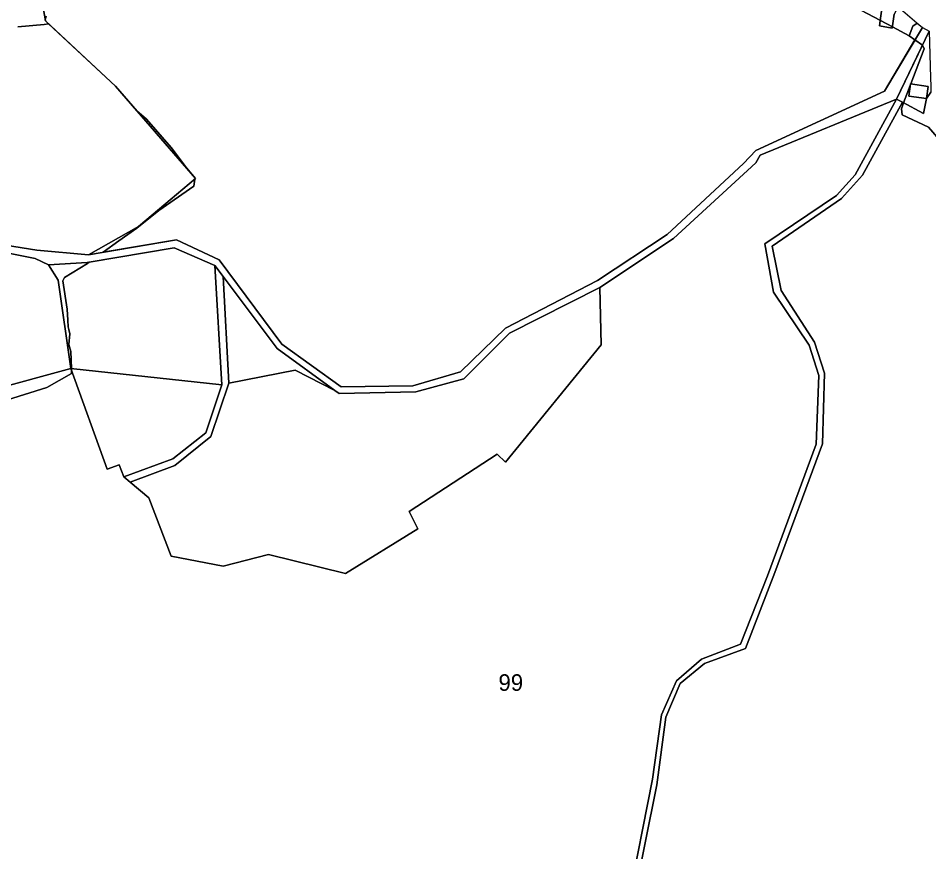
# Model space of a CAD drawing. Extents: x -502026 to -497664, y -1143484 to -1138019.
# Drawn here: x -498405.5 to -497965.8, y -1139162.9 to -1138760.2 of the extents above; entities that cross this region are included whole.
import ezdxf

# ---------------------------------------------------------------- set-up
doc = ezdxf.new("R2010")
doc.units = 0
for name, color, linetype in [('43', 7, 'Continuous'), ('55', 7, 'Continuous'), ('62', 7, 'Continuous'), ('7', 7, 'Continuous')]:
    doc.layers.add(name, color=color, linetype=linetype)

msp = doc.modelspace()

# ---------------------------------------------------------------- linework, layer by layer
at = {"layer": '43'}
for points in [[(-497980.6, -1138754.72), (-497971.57, -1138762.37), (-497968.95, -1138764.58), (-497987.18, -1138795.48), (-498049.29, -1138824.02), (-498055.3, -1138830.39), (-498092.16, -1138864.7), (-498125.79, -1138886.81), (-498170.31, -1138909.96), (-498192.01, -1138930.96), (-498214.91, -1138937.8), (-498249.65, -1138938.27), (-498278.19, -1138917.67), (-498308.48, -1138876.87), (-498329.06, -1138867.27), (-498371.63, -1138874.41), (-498347.43, -1138860.73), (-498319.89, -1138837.58), (-498358.52, -1138793.04), (-498392.35, -1138761.47), (-498396.46, -1138737.8)], [(-497988.16, -1138753.07), (-497989.58, -1138763.83), (-497983.52, -1138764.9), (-497982.54, -1138758.23)], [(-498108.78, -1139188.21), (-498097.11, -1139130.62), (-498092.86, -1139097.89), (-498085.89, -1139081.65), (-498074.21, -1139071.99), (-498054.27, -1139064.63), (-498040.16, -1139028.04), (-498017.12, -1138965.8), (-498016.18, -1138931.71), (-498021.06, -1138916.63), (-498037.13, -1138891.67), (-498041.54, -1138870.32), (-498008.04, -1138847.29), (-497997.8, -1138835.99), (-497978.52, -1138800.78), (-497968.32, -1138806.18), (-497966.9, -1138799.01), (-497964.86, -1138795.85)], [(-498491.66, -1138959.88), (-498380.15, -1138929.34), (-498362.55, -1138977.96), (-498356.81, -1138975.87), (-498354.51, -1138981.72), (-498351.49, -1138984.29), (-498342.48, -1138991.95), (-498331.71, -1139020.04), (-498306.56, -1139024.84), (-498284.64, -1139019.2), (-498247.48, -1139028.49), (-498212.52, -1139006.88), (-498216.8, -1138998.53), (-498174.32, -1138970.86), (-498170.25, -1138974.62), (-498123.96, -1138917.91), (-498124.63, -1138890.31), (-498089.13, -1138866.66), (-498049.3, -1138830.09), (-498047.24, -1138826.3), (-497981.46, -1138799.22), (-498001.46, -1138835.83), (-498010.36, -1138845.86), (-498045.06, -1138869.12), (-498040.89, -1138892.51), (-498023.56, -1138918.19), (-498018.97, -1138932.71), (-498020.25, -1138965.96), (-498043.68, -1139029.65), (-498056.83, -1139062.65), (-498075.61, -1139069.85), (-498087.59, -1139080.28), (-498094.9, -1139096.78), (-498099.18, -1139127.75), (-498111.07, -1139187.37)]]:
    msp.add_lwpolyline(points, dxfattribs=at)
for points in [[(-497980.6, -1138754.72), (-497982.54, -1138758.23), (-497983.52, -1138764.9), (-497989.58, -1138763.83), (-497988.16, -1138753.07), (-497988.29, -1138751.04), (-497990.02, -1138746.73)], [(-498310.63, -1138879.58), (-498307.13, -1138937.24), (-498380.15, -1138929.34), (-498386.17, -1138886.68), (-498390.89, -1138879.27), (-498372.3, -1138878.19), (-498330.14, -1138871.18)], [(-498252.63, -1138940.02), (-498271.75, -1138930.14), (-498303.89, -1138936.51), (-498306.57, -1138884.97), (-498280.42, -1138919.66)], [(-498351.49, -1138984.29), (-498329.96, -1138976.29), (-498312.45, -1138962.3), (-498303.89, -1138936.51), (-498271.75, -1138930.14), (-498252.63, -1138940.02), (-498250.48, -1138941.41), (-498213.51, -1138940.63), (-498190.35, -1138934.38), (-498168.22, -1138912.36), (-498124.63, -1138890.31), (-498123.96, -1138917.91), (-498170.25, -1138974.62), (-498174.32, -1138970.86), (-498216.8, -1138998.53), (-498212.52, -1139006.88), (-498247.48, -1139028.49), (-498284.64, -1139019.2), (-498306.56, -1139024.84), (-498331.71, -1139020.04), (-498342.48, -1138991.95)], [(-498307.13, -1138937.24), (-498314.85, -1138960.52), (-498330.82, -1138973.05), (-498354.51, -1138981.72), (-498356.81, -1138975.87), (-498362.55, -1138977.96), (-498380.15, -1138929.34)]]:
    msp.add_lwpolyline(points, close=True, dxfattribs=at)
at = {"layer": '55'}
for points in [[(-497965.03, -1138788.96), (-497964.93, -1138792.93), (-497964.86, -1138795.85), (-497966.9, -1138799.01), (-497966.09, -1138793.1), (-497974.72, -1138791.92), (-497975.53, -1138797.83), (-497966.9, -1138799.01), (-497968.32, -1138806.18), (-497978.52, -1138800.78), (-497981.46, -1138799.22), (-497965.6, -1138766.42)], [(-497966.9, -1138799.01), (-497975.53, -1138797.83), (-497974.72, -1138791.92), (-497966.09, -1138793.1)], [(-498306.57, -1138884.97), (-498303.89, -1138936.51), (-498312.45, -1138962.3), (-498329.96, -1138976.29), (-498351.49, -1138984.29), (-498354.51, -1138981.72), (-498330.82, -1138973.05), (-498314.85, -1138960.52), (-498307.13, -1138937.24), (-498310.63, -1138879.58)]]:
    msp.add_lwpolyline(points, close=True, dxfattribs=at)
msp.add_lwpolyline([(-498111.07, -1139187.37), (-498099.18, -1139127.75), (-498094.9, -1139096.78), (-498087.59, -1139080.28), (-498075.61, -1139069.85), (-498056.83, -1139062.65), (-498043.68, -1139029.65), (-498020.25, -1138965.96), (-498018.97, -1138932.71), (-498023.56, -1138918.19), (-498040.89, -1138892.51), (-498045.06, -1138869.12), (-498010.36, -1138845.86), (-498001.46, -1138835.83), (-497981.46, -1138799.22), (-497978.52, -1138800.78), (-497997.8, -1138835.99), (-498008.04, -1138847.29), (-498041.54, -1138870.32), (-498037.13, -1138891.67), (-498021.06, -1138916.63), (-498016.18, -1138931.71), (-498017.12, -1138965.8), (-498040.16, -1139028.04), (-498054.27, -1139064.63), (-498074.21, -1139071.99), (-498085.89, -1139081.65), (-498092.86, -1139097.89), (-498097.11, -1139130.62), (-498108.78, -1139188.21)], dxfattribs=at)
at = {"layer": '62'}
for points in [[(-497998.66, -1138756.25), (-497989.24, -1138761.24), (-497983.43, -1138764.31), (-497975.28, -1138768.62), (-497972.52, -1138770.63), (-497987.18, -1138795.48), (-498049.29, -1138824.02), (-498055.3, -1138830.39), (-498092.16, -1138864.7), (-498125.79, -1138886.81), (-498170.31, -1138909.96), (-498192.01, -1138930.96), (-498214.91, -1138937.8), (-498249.65, -1138938.27), (-498278.19, -1138917.67), (-498308.48, -1138876.87), (-498329.06, -1138867.27), (-498364.53, -1138873.22), (-498356.93, -1138867.79), (-498348.31, -1138861.62), (-498337.69, -1138853.12), (-498320.69, -1138841.25), (-498320.25, -1138837.88), (-498319.89, -1138837.58), (-498324.27, -1138832.53), (-498331.72, -1138822.62), (-498343.62, -1138809), (-498348.21, -1138804.93), (-498358.52, -1138793.04), (-498390.9, -1138762.82), (-498392.35, -1138761.47), (-498392.44, -1138760.97), (-498392.06, -1138759.25)], [(-497980.6, -1138754.72), (-497971.57, -1138762.37), (-497971.42, -1138762.5), (-497973.56, -1138764), (-497975.28, -1138768.62), (-497983.43, -1138764.31), (-497989.24, -1138761.24), (-497998.66, -1138756.25)], [(-498392.06, -1138759.25), (-498392.44, -1138760.97), (-498392.35, -1138761.47), (-498390.9, -1138762.82), (-498392.91, -1138763.12), (-498405.66, -1138764.37)], [(-497960.79, -1138818.84), (-497965.94, -1138812.87), (-497978.69, -1138806.87), (-497979.09, -1138803.87), (-497978.01, -1138801.05), (-497974.83, -1138792.71), (-497974.54, -1138791.94), (-497968.06, -1138775), (-497968.9, -1138773.25), (-497972.52, -1138770.63), (-497975.28, -1138768.62), (-497973.56, -1138764), (-497971.42, -1138762.5), (-497968.95, -1138764.58), (-497965.6, -1138766.42)], [(-498405.66, -1138764.37), (-498392.91, -1138763.12), (-498390.9, -1138762.82), (-498358.52, -1138793.04), (-498348.21, -1138804.93), (-498343.62, -1138809), (-498331.72, -1138822.62), (-498324.27, -1138832.53), (-498319.89, -1138837.58), (-498320.25, -1138837.88), (-498320.69, -1138841.25), (-498337.69, -1138853.12), (-498348.31, -1138861.62), (-498356.93, -1138867.79), (-498364.53, -1138873.22), (-498329.06, -1138867.27), (-498308.48, -1138876.87), (-498278.19, -1138917.67), (-498249.65, -1138938.27), (-498214.91, -1138937.8), (-498192.01, -1138930.96), (-498170.31, -1138909.96), (-498125.79, -1138886.81), (-498092.16, -1138864.7), (-498055.3, -1138830.39), (-498049.29, -1138824.02), (-497987.18, -1138795.48), (-497972.52, -1138770.63), (-497968.9, -1138773.25), (-497981.46, -1138799.22), (-498047.24, -1138826.3), (-498049.3, -1138830.09), (-498089.13, -1138866.66), (-498124.63, -1138890.31), (-498168.22, -1138912.36), (-498190.35, -1138934.38), (-498213.51, -1138940.63), (-498250.48, -1138941.41), (-498252.63, -1138940.02), (-498280.42, -1138919.66), (-498306.57, -1138884.97), (-498310.63, -1138879.58), (-498330.14, -1138871.18), (-498371.24, -1138878.01), (-498372.09, -1138878.62), (-498383.12, -1138885.5), (-498384, -1138887.12), (-498381.87, -1138900.75), (-498381.6, -1138906.06), (-498381.44, -1138909.25), (-498381.13, -1138910.48), (-498380.59, -1138912.62), (-498381, -1138917.75), (-498380.16, -1138921.12), (-498379.84, -1138929.37), (-498379.83, -1138929.57), (-498379.81, -1138930.29), (-498379.75, -1138931.75), (-498391.62, -1138938.62), (-498410.75, -1138944.5)], [(-498410.75, -1138944.5), (-498391.62, -1138938.62), (-498379.75, -1138931.75), (-498379.81, -1138930.29), (-498379.83, -1138929.57), (-498379.84, -1138929.37), (-498380.16, -1138921.12), (-498381, -1138917.75), (-498380.59, -1138912.62), (-498381.13, -1138910.48), (-498381.44, -1138909.25), (-498381.6, -1138906.06), (-498381.87, -1138900.75), (-498384, -1138887.12), (-498383.12, -1138885.5), (-498372.09, -1138878.62), (-498371.24, -1138878.01), (-498330.14, -1138871.18), (-498310.63, -1138879.58), (-498306.57, -1138884.97), (-498280.42, -1138919.66), (-498252.63, -1138940.02), (-498250.48, -1138941.41), (-498213.51, -1138940.63), (-498190.35, -1138934.38), (-498168.22, -1138912.36), (-498124.63, -1138890.31), (-498089.13, -1138866.66), (-498049.3, -1138830.09), (-498047.24, -1138826.3), (-497981.46, -1138799.22), (-497968.9, -1138773.25), (-497968.06, -1138775), (-497974.54, -1138791.94), (-497974.83, -1138792.71), (-497978.01, -1138801.05), (-497979.09, -1138803.87), (-497978.69, -1138806.87), (-497965.94, -1138812.87), (-497960.79, -1138818.84)]]:
    msp.add_lwpolyline(points, dxfattribs=at)
at = {"layer": '7'}
for points in [[(-498371.63, -1138874.41), (-498396.55, -1138872.26), (-498418.98, -1138868.62), (-498446.37, -1138838.19), (-498477, -1138818.54), (-498503.51, -1138801.96), (-498535.67, -1138787.24), (-498490.02, -1138774.59), (-498494.11, -1138757.49), (-498470.02, -1138754.55), (-498396.46, -1138737.8), (-498392.35, -1138761.47), (-498358.52, -1138793.04), (-498319.89, -1138837.58), (-498347.43, -1138860.73)], [(-498390.89, -1138879.27), (-498386.17, -1138886.68), (-498380.15, -1138929.34), (-498491.66, -1138959.88), (-498507.42, -1138971.76), (-498517.66, -1138984.02), (-498515.1, -1138971.23), (-498521.61, -1138933.37), (-498532.93, -1138898.4), (-498483.29, -1138881.15), (-498447.06, -1138871.85), (-498428.87, -1138869.97), (-498397.35, -1138876.3)]]:
    msp.add_lwpolyline(points, close=True, dxfattribs=at)
msp.add_lwpolyline([(-498418.98, -1138868.62), (-498396.55, -1138872.26), (-498371.63, -1138874.41), (-498329.06, -1138867.27), (-498308.48, -1138876.87), (-498278.19, -1138917.67), (-498249.65, -1138938.27), (-498214.91, -1138937.8), (-498192.01, -1138930.96), (-498170.31, -1138909.96), (-498125.79, -1138886.81), (-498092.16, -1138864.7), (-498055.3, -1138830.39), (-498049.29, -1138824.02), (-497987.18, -1138795.48), (-497968.95, -1138764.58), (-497965.6, -1138766.42), (-497981.46, -1138799.22), (-498047.24, -1138826.3), (-498049.3, -1138830.09), (-498089.13, -1138866.66), (-498124.63, -1138890.31), (-498168.22, -1138912.36), (-498190.35, -1138934.38), (-498213.51, -1138940.63), (-498250.48, -1138941.41), (-498252.63, -1138940.02), (-498280.42, -1138919.66), (-498306.57, -1138884.97), (-498310.63, -1138879.58), (-498330.14, -1138871.18), (-498372.3, -1138878.19), (-498390.89, -1138879.27), (-498397.35, -1138876.3), (-498428.87, -1138869.97)], dxfattribs=at)

# ---------------------------------------------------------------- texts
at = {"layer": '62'}
msp.add_text('99', height=8, dxfattribs=at).set_placement((-498173.62, -1139085.13))

doc.saveas('drawing.dxf')
